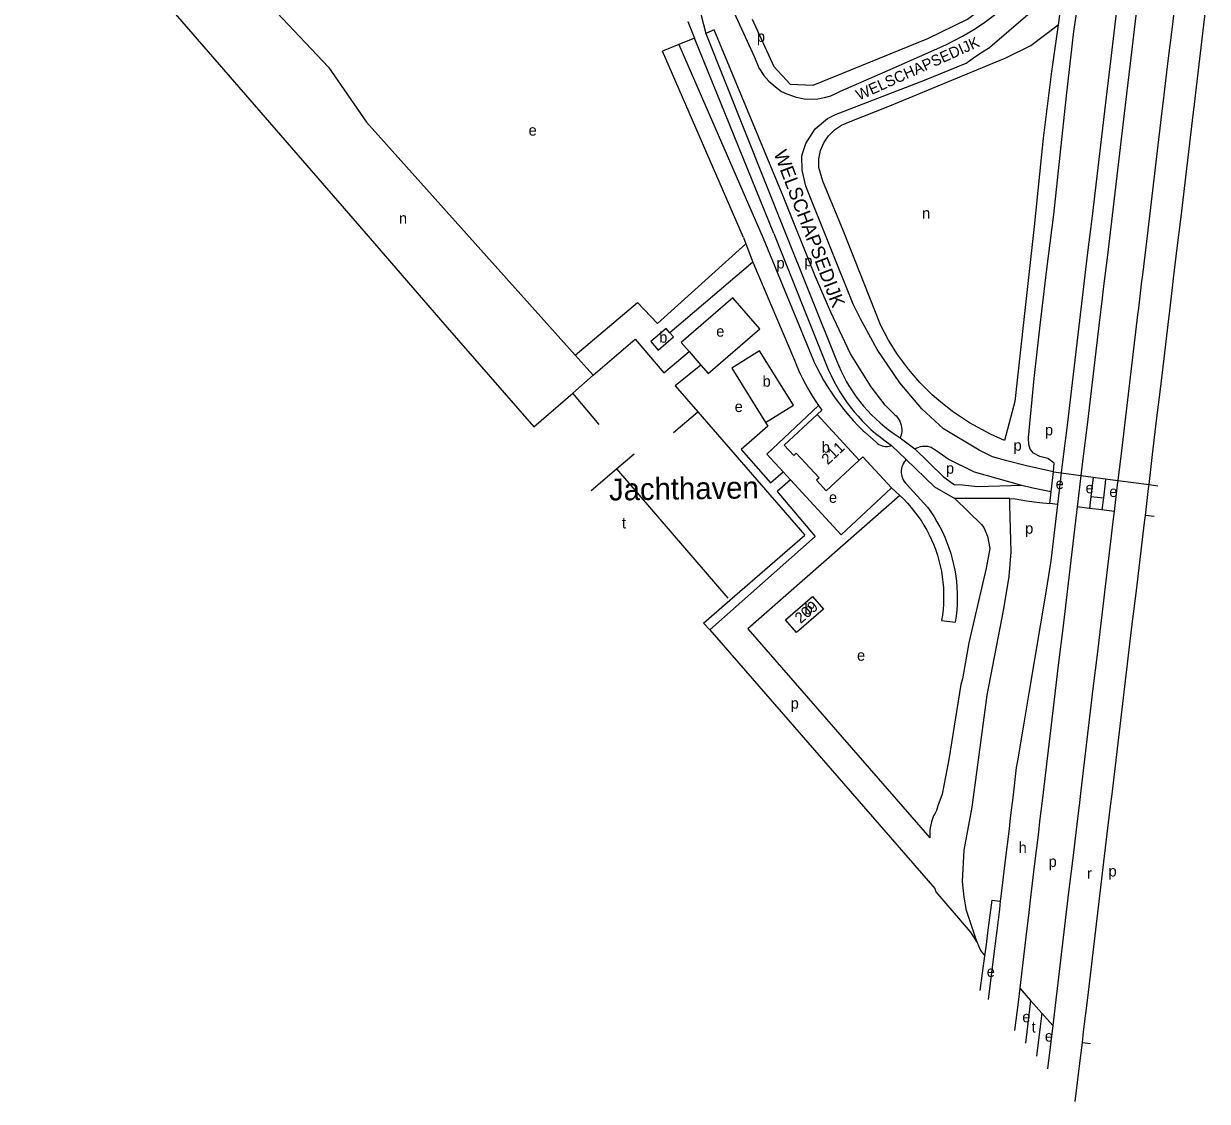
# Model space of a CAD drawing. Extents: x 156066 to 157805, y 383432 to 385631.
# Drawn here: x 157346 to 157778.7, y 383431.9 to 383825.9 of the extents above; entities that cross this region are included whole.
import ezdxf

# ---------------------------------------------------------------- set-up
doc = ezdxf.new("R2010")
doc.units = 0
for name, color, linetype in [('BLT_Basislijn', 7, 'Continuous'), ('BLT_Bebouwing', 7, 'Continuous'), ('BLT_Centroide', 7, 'Continuous'), ('BLT_Huisnummer', 7, 'Continuous'), ('BLT_Straatnaam', 7, 'Continuous'), ('BLT_Straatnaam_verkleind', 7, 'Continuous'), ('BLT_Terrein_beschrifting', 7, 'Continuous'), ('BLT_Vlakafsluiter', 7, 'Continuous')]:
    doc.layers.add(name, color=color, linetype=linetype)

msp = doc.modelspace()

# ---------------------------------------------------------------- linework, layer by layer
at = {"layer": 'BLT_Basislijn'}
for p, q in [((157457.51, 383809.98), (157438.58, 383829.98)), ((157593.54, 383829.35), (157595.4, 383822.3)), ((157588.75, 383826.7), (157591.23, 383820.59)), ((157591.23, 383820.59), (157585.48, 383818.23)), ((157620.2, 383749.22), (157591.23, 383820.59)), ((157595.4, 383822.3), (157623.9, 383750.73)), ((157585.48, 383818.23), (157579.57, 383815.8)), ((157609.12, 383747.66), (157579.57, 383815.8)), ((157609.12, 383747.66), (157609.99, 383745.39)), ((157620.2, 383749.22), (157639.4, 383701.34)), ((157623.9, 383750.73), (157643.13, 383702.79)), ((157609.99, 383745.39), (157612.52, 383738.71)), ((157612.52, 383738.71), (157582.28, 383712.84)), ((157612.52, 383738.71), (157627.82, 383702.89)), ((157554.26, 383697.33), (157569.55, 383710.59)), ((157547.66, 383704.7), (157554.26, 383697.33)), ((157589.26, 383706.06), (157593.56, 383701.09)), ((157546.74, 383690.8), (157554.26, 383697.33)), ((157556.36, 383679.38), (157546.74, 383690.8)), ((157660.91, 383686.48), (157664.41, 383683.03)), ((157583.53, 383676.38), (157592.43, 383684.01)), ((157592.43, 383684.01), (157631.6, 383638.86)), ((157636.09, 383682.98), (157637.81, 383684.64)), ((157653.46, 383676.5), (157657.69, 383672.85)), ((157666.44, 383674.45), (157671.74, 383670.48)), ((157668.6, 383666.56), (157663.31, 383671.71)), ((157562.77, 383663.15), (157569.19, 383668.67)), ((157651.49, 383666.3), (157652.78, 383667.56)), ((157652.78, 383667.56), (157663.3, 383656.22)), ((157668.6, 383666.56), (157668.05, 383665.77)), ((157553.51, 383655.2), (157562.77, 383663.15)), ((157562.77, 383663.15), (157603.47, 383615.84)), ((157623.62, 383662.07), (157626.29, 383659.16)), ((157721.64, 383654.79), (157722.42, 383662.04)), ((157722.42, 383662.04), (157725.33, 383661.66)), ((157732.51, 383660.7), (157736.97, 383660.11)), ((157663.3, 383656.22), (157666.29, 383653.4)), ((157668.74, 383657.53), (157676.42, 383649.08)), ((157736.97, 383660.11), (157741.52, 383659.51)), ((157741.52, 383659.51), (157745.99, 383658.92)), ((157757.39, 383657.41), (157760.57, 383656.99)), ((157666.29, 383653.4), (157610.71, 383604.63)), ((157706.46, 383652.32), (157686.36, 383652.25)), ((157721.11, 383650.52), (157721.64, 383654.79)), ((157736.13, 383653.03), (157740.69, 383652.49)), ((157723.95, 383650.16), (157721.11, 383650.52)), ((157735.61, 383648.7), (157731.14, 383649.26)), ((157740.16, 383648.12), (157735.61, 383648.7)), ((157744.63, 383647.56), (157740.16, 383648.12)), ((157759.21, 383645.73), (157756.04, 383646.13)), ((157604.13, 383615.09), (157631.6, 383638.86)), ((157596.81, 383604.28), (157679.07, 383509.71)), ((157610.71, 383604.63), (157677.29, 383528.31)), ((157681.54, 383607.66), (157686.57, 383607.13)), ((157689.24, 383586.43), (157688.6, 383584.32)), ((157680.25, 383539.93), (157679.74, 383538.29)), ((157679.07, 383509.71), (157679.5, 383508.54)), ((157695.7, 383472.46), (157697.43, 383485.16)), ((157710.11, 383473.27), (157714.11, 383468.75)), ((157714.11, 383468.75), (157718.18, 383464.15)), ((157718.18, 383464.15), (157722.17, 383459.64)), ((157733.01, 383453.43), (157735.99, 383453.06))]:
    msp.add_line(p, q, dxfattribs=at)
for points in [[(157722.42, 383662.04), (157722.67, 383665.22), (157720.34, 383666.94), (157717.53, 383667.7), (157715.18, 383668.86), (157713.89, 383670.39), (157713.43, 383672.1), (157713.37, 383674.52), (157715.42, 383696.22), (157717.58, 383715.61), (157720.01, 383736.12), (157722.63, 383756.17), (157727.24, 383799.44), (157729.87, 383823.04), (157736.09, 383864.84), (157743.57, 383910.3), (157751.03, 383956.19), (157757.33, 384004.1), (157760.96, 384035.06), (157763.25, 384061.94)], [(157346.04, 383893.34), (157407.92, 383821.99), (157470.36, 383750), (157500, 383715.82)], [(157612.35, 383827.53), (157620.27, 383810.26), (157626.26, 383803.73), (157634.61, 383803.39), (157676.59, 383820.43), (157691.04, 383827.5), (157700.2, 383834.34), (157708.27, 383840.98)], [(157699.19, 383817.3), (157713.05, 383829.25), (157724.1, 383841.83)], [(157726.44, 383841.44), (157725.63, 383836.21), (157724.13, 383825.48)], [(157603.63, 383834.36), (157608.4, 383823.97), (157613.18, 383813.58), (157614.72, 383809.78), (157616.56, 383806.93), (157618.4, 383804.81), (157620.8, 383802.78), (157623.01, 383801.12), (157625.04, 383800.2), (157628.08, 383799.09), (157631.39, 383798.45), (157633.99, 383798.32), (157636.28, 383798.45), (157638.81, 383798.86), (157641.04, 383799.51), (157642.95, 383800.29), (157644.67, 383801.16)], [(157644.67, 383801.16), (157663.88, 383809.64), (157683.09, 383818.12), (157689.23, 383821.3), (157693.97, 383824.16), (157697.41, 383826.47), (157700.75, 383828.94), (157705.02, 383832.45), (157710.41, 383837.51)], [(157753.46, 383836.1), (157751.98, 383823.69), (157750.49, 383811.28), (157749.19, 383800.26), (157748.08, 383790.96), (157746.6, 383778.55), (157745.11, 383766.13), (157743.63, 383753.72), (157742.15, 383741.31), (157740.66, 383728.9), (157740.26, 383725.56)], [(157746.26, 383836.96), (157744.78, 383824.55), (157743.29, 383812.14), (157741.99, 383801.12)], [(157767.28, 383837.14), (157765.8, 383824.73), (157764.31, 383812.32), (157762.83, 383799.91), (157762.68, 383798.65), (157762.11, 383793.85), (157760.62, 383781.44), (157759.14, 383769.03), (157757.66, 383756.61), (157756.17, 383744.2), (157754.85, 383733.12), (157754.69, 383731.79), (157753.51, 383721.89)], [(157764.72, 383718.78), (157766.11, 383730.43), (157766.27, 383731.75), (157767.59, 383742.84), (157769.08, 383755.25), (157770.56, 383767.66), (157772.04, 383780.07), (157773.53, 383792.49), (157774.1, 383797.28), (157774.25, 383798.54), (157775.73, 383810.95), (157777.21, 383823.36), (157778.7, 383835.78)], [(157704.52, 383673.56), (157699.44, 383675.78), (157691.82, 383679.96), (157685.5, 383684.15), (157680.51, 383688.11), (157678.13, 383690.22), (157673.62, 383694.72), (157669.46, 383699.53), (157665.42, 383704.98), (157662.15, 383710.22), (157659.25, 383715.79), (157645.65, 383750), (157638.16, 383768.26), (157636.68, 383773.34), (157636.68, 383776.48), (157637.34, 383779.55), (157638.55, 383782.3), (157640.22, 383784.9), (157642.39, 383787.1), (157644.98, 383788.79), (157647.55, 383789.83), (157662.64, 383795.84), (157705.05, 383813.33), (157714.13, 383817.93), (157724.13, 383825.48)], [(157724.13, 383825.48), (157721.73, 383808.33), (157718.74, 383784.05), (157715.44, 383751.67), (157711.54, 383716.59), (157708.39, 383687.81), (157704.52, 383673.56)], [(157660.91, 383686.48), (157655.83, 383693.14), (157648.3, 383705.21), (157641.02, 383720.37), (157635.43, 383733.33), (157623.71, 383762.8), (157598.48, 383823.56), (157595.4, 383822.3)], [(157585.48, 383818.23), (157616.32, 383747.49), (157634.69, 383702.75), (157634.79, 383702.59)], [(157690.55, 383811.48), (157693.21, 383813.38), (157695.92, 383815.21), (157698.67, 383816.97), (157699.19, 383817.3)], [(157457.51, 383809.98), (157471.4, 383789.83), (157547.66, 383704.7)], [(157642.79, 383792.66), (157675.36, 383805.22), (157690.55, 383811.48)], [(157741.99, 383801.12), (157740.88, 383791.82), (157739.4, 383779.41), (157737.91, 383767), (157736.43, 383754.58), (157734.95, 383742.17), (157733.46, 383729.76), (157731.98, 383717.35), (157730.5, 383704.94), (157729.01, 383692.53), (157727.53, 383680.11), (157726.05, 383667.7), (157725.33, 383661.66)], [(157705.38, 383666.03), (157700.21, 383667.59), (157695.26, 383669.98), (157682.29, 383677.72), (157674.33, 383685.12), (157666.3, 383694.54), (157658.02, 383706.79), (157651.94, 383717.98), (157649.22, 383723.31), (157631.92, 383766.52), (157630.54, 383772.32), (157630.5, 383777.38), (157630.82, 383778.77), (157631.89, 383782.08), (157635.3, 383787.49), (157639.86, 383791.16), (157642.79, 383792.66)], [(157547.66, 383704.7), (157570.35, 383723.98), (157577.66, 383716.29), (157609.99, 383745.39)], [(157605.3, 383725.7), (157586.4, 383709.37), (157589.26, 383706.06)], [(157593.56, 383701.09), (157596.2, 383698.03), (157615.1, 383714.36), (157605.3, 383725.7)], [(157740.26, 383725.56), (157739.18, 383716.49), (157737.7, 383704.08), (157736.21, 383691.66), (157734.73, 383679.25), (157733.25, 383666.84), (157732.51, 383660.7)], [(157753.51, 383721.89), (157753.21, 383719.38), (157751.73, 383706.97), (157750.24, 383694.56), (157748.76, 383682.14), (157747.28, 383669.73), (157745.99, 383658.92)], [(157757.39, 383657.41), (157758.7, 383668.37), (157760.18, 383680.78), (157761.66, 383693.19), (157763.14, 383705.6), (157764.63, 383718.02), (157764.72, 383718.78)], [(157500, 383715.82), (157532.49, 383678.45), (157546.74, 383690.8)], [(157569.55, 383710.59), (157580.09, 383698.24), (157589.26, 383706.06)], [(157593.56, 383701.09), (157584.2, 383693.49), (157592.43, 383684.01)], [(157627.82, 383702.89), (157628.71, 383700.63), (157629.67, 383698.41), (157630.71, 383696.21), (157631.81, 383694.06), (157632.99, 383691.94), (157634.24, 383689.86), (157635.55, 383687.82), (157636.58, 383686.35)], [(157634.79, 383702.59), (157635.93, 383700.22), (157637.14, 383697.9), (157638.42, 383695.6), (157639.77, 383693.35), (157641.19, 383691.15), (157642.68, 383688.98), (157644.23, 383686.86), (157645.84, 383684.79), (157647.52, 383682.77), (157649.26, 383680.8), (157651.05, 383678.89), (157652.91, 383677.03), (157653.46, 383676.5)], [(157639.4, 383701.34), (157640.25, 383699.27), (157641.17, 383697.23), (157642.16, 383695.22), (157643.23, 383693.25), (157644.36, 383691.32), (157645.57, 383689.43), (157646.84, 383687.58), (157648.17, 383685.79), (157649.57, 383684.04), (157651.03, 383682.34), (157652.55, 383680.69), (157654.12, 383679.1), (157655.76, 383677.57), (157657.45, 383676.1), (157659.18, 383674.68), (157660.97, 383673.33), (157662.8, 383672.05), (157663.31, 383671.71)], [(157643.13, 383702.79), (157643.95, 383700.78), (157644.85, 383698.81), (157645.81, 383696.87), (157646.85, 383694.97), (157647.96, 383693.11), (157649.14, 383691.29), (157650.38, 383689.51), (157651.68, 383687.78), (157653.05, 383686.1), (157654.49, 383684.48), (157655.98, 383682.9), (157657.52, 383681.39), (157659.12, 383679.93), (157660.78, 383678.53), (157662.49, 383677.19), (157664.24, 383675.92), (157666.04, 383674.71), (157666.44, 383674.45)], [(157636.58, 383686.35), (157617.64, 383668.56), (157623.62, 383662.07)], [(157636.58, 383686.35), (157636.94, 383685.83), (157637.81, 383684.64)], [(157664.41, 383683.03), (157664.97, 383682.49), (157665.47, 383681.89), (157665.91, 383681.24), (157666.27, 383680.55), (157666.57, 383679.83), (157666.79, 383679.08), (157666.93, 383678.32), (157667, 383677.54), (157666.98, 383676.76), (157666.88, 383675.98), (157666.71, 383675.22), (157666.44, 383674.45)], [(157617.21, 383680.1), (157618.1, 383678.71), (157608.31, 383670.23), (157619.08, 383658.03), (157623.62, 383662.07)], [(157657.69, 383672.85), (157658.16, 383672.42), (157658.68, 383672.05), (157659.25, 383671.76), (157659.85, 383671.53), (157660.47, 383671.38), (157661.1, 383671.31), (157661.74, 383671.32), (157662.38, 383671.41), (157662.99, 383671.58), (157663.31, 383671.71)], [(157679.84, 383669.62), (157678.86, 383670.23), (157677.75, 383670.96), (157676.67, 383671.28), (157675.9, 383671.33), (157674.61, 383671.31), (157673.72, 383671.13), (157672.72, 383670.86), (157671.74, 383670.48)], [(157671.74, 383670.48), (157682.18, 383660.39), (157686.28, 383657.27)], [(157710.87, 383657.08), (157693.63, 383661.97), (157683.95, 383666.73), (157679.84, 383669.62)], [(157668.05, 383665.77), (157667.66, 383665.18), (157667.34, 383664.55), (157667.09, 383663.89), (157666.92, 383663.21), (157666.83, 383662.51), (157666.82, 383661.8), (157666.89, 383661.1), (157667.03, 383660.41), (157667.25, 383659.74), (157667.55, 383659.1), (157667.92, 383658.49), (157668.35, 383657.93), (157668.74, 383657.53)], [(157668.6, 383666.56), (157678.92, 383656.59), (157686.36, 383652.25)], [(157722.42, 383662.04), (157713.07, 383664.15), (157705.38, 383666.03)], [(157725.33, 383661.66), (157724.56, 383655.29), (157723.95, 383650.16)], [(157732.51, 383660.7), (157731.76, 383654.43), (157731.14, 383649.26)], [(157626.29, 383659.16), (157621.49, 383654.91), (157635.33, 383638.36), (157596.81, 383604.28)], [(157626.29, 383659.16), (157644.84, 383639.03), (157663.3, 383656.22)], [(157710.87, 383657.08), (157694.71, 383656.57), (157689.19, 383657.14), (157686.28, 383657.27)], [(157721.64, 383654.79), (157714.94, 383656.04), (157710.87, 383657.08)], [(157736.97, 383660.11), (157736.13, 383653.03)], [(157741.52, 383659.51), (157741.33, 383657.85), (157740.69, 383652.49)], [(157745.99, 383658.92), (157745.79, 383657.32), (157744.63, 383647.56)], [(157756.04, 383646.13), (157757.21, 383655.96), (157757.39, 383657.41)], [(157666.29, 383653.4), (157667.73, 383652), (157669.11, 383650.55), (157670.44, 383649.04), (157671.7, 383647.48), (157672.9, 383645.86), (157674.04, 383644.21), (157675.11, 383642.5), (157676.11, 383640.76), (157677.04, 383638.98), (157677.9, 383637.16), (157678.68, 383635.31), (157679.4, 383633.43), (157680.03, 383631.53), (157680.59, 383629.6), (157681.08, 383627.65), (157681.48, 383625.68), (157681.81, 383623.7), (157682.05, 383621.7), (157682.22, 383619.7), (157682.31, 383617.69), (157682.32, 383615.68), (157682.24, 383613.67), (157682.09, 383611.67), (157681.86, 383609.67), (157681.54, 383607.66)], [(157686.36, 383652.25), (157696.14, 383642.82), (157697.01, 383641.66), (157698.32, 383638.54), (157699.15, 383634.06), (157697.89, 383626.88), (157691.55, 383599.57), (157689.24, 383586.43)], [(157694.51, 383490.02), (157690.68, 383501.76), (157689.77, 383506.58), (157689.24, 383512.36), (157689.81, 383523.73), (157692.76, 383539.46), (157698.17, 383580.44), (157704.26, 383612), (157706.23, 383623.8), (157707.05, 383632.82), (157706.56, 383649.89), (157706.46, 383652.32)], [(157706.46, 383652.32), (157708.42, 383652.14), (157712.61, 383651.43), (157717.32, 383650.88), (157721.11, 383650.52)], [(157736.13, 383653.03), (157735.61, 383648.7)], [(157740.69, 383652.49), (157740.16, 383648.12)], [(157676.42, 383649.08), (157677.64, 383647.37), (157678.79, 383645.61), (157679.88, 383643.8), (157680.9, 383641.96), (157681.85, 383640.08), (157682.72, 383638.17), (157683.52, 383636.22), (157684.25, 383634.24), (157684.9, 383632.24), (157685.47, 383630.22), (157685.97, 383628.17), (157686.39, 383626.11), (157686.73, 383624.03), (157686.99, 383621.94), (157687.17, 383619.85), (157687.27, 383617.74), (157687.29, 383615.64), (157687.24, 383613.53), (157687.1, 383611.43), (157686.88, 383609.34), (157686.57, 383607.13)], [(157723.95, 383650.16), (157723.08, 383642.88), (157721.6, 383630.47), (157721.3, 383627.98), (157719.64, 383618.11), (157717.57, 383605.77), (157715.5, 383593.43), (157713.43, 383581.09), (157711.36, 383568.75), (157709.29, 383556.4), (157708.88, 383553.94), (157707.69, 383544.01), (157706.68, 383535.53), (157706.21, 383531.59), (157704.72, 383519.18), (157703.24, 383506.77), (157703.03, 383505.06)], [(157731.14, 383649.26), (157730.28, 383642.02), (157728.8, 383629.61), (157727.31, 383617.19), (157725.83, 383604.78), (157724.35, 383592.37), (157722.86, 383579.96), (157721.38, 383567.55), (157719.9, 383555.14), (157718.41, 383542.72), (157717.4, 383534.25), (157716.93, 383530.31), (157715.45, 383517.9), (157713.96, 383505.49), (157713.42, 383500.96), (157712.48, 383493.08), (157711, 383480.67), (157710.11, 383473.27)], [(157744.63, 383647.56), (157744.31, 383644.91), (157742.83, 383632.5), (157741.35, 383620.09), (157739.86, 383607.67), (157738.38, 383595.26), (157736.9, 383582.85), (157735.41, 383570.44), (157733.93, 383558.03), (157732.45, 383545.62), (157731.92, 383541.19), (157730.96, 383533.2), (157729.48, 383520.79), (157728, 383508.38), (157726.52, 383495.97), (157725.03, 383483.56), (157723.55, 383471.15), (157722.17, 383459.64)], [(157733.01, 383453.43), (157733.49, 383457.37), (157734.97, 383469.78), (157736.45, 383482.19), (157737.93, 383494.6), (157739.42, 383507.02), (157740.9, 383519.43), (157742.38, 383531.84), (157743.34, 383539.83), (157743.87, 383544.25), (157745.35, 383556.66), (157746.83, 383569.07), (157748.32, 383581.49), (157749.8, 383593.9), (157751.28, 383606.31), (157752.76, 383618.72), (157754.25, 383631.13), (157755.73, 383643.55), (157756.04, 383646.13)], [(157596.81, 383604.28), (157594.5, 383606.76), (157604.13, 383615.09)], [(157688.6, 383584.32), (157684.19, 383556.86), (157681.73, 383544.19), (157680.25, 383539.93)], [(157679.74, 383538.29), (157679.16, 383537.31), (157678.66, 383536.29), (157678.23, 383535.24), (157677.87, 383534.16), (157677.59, 383533.06), (157677.39, 383531.95), (157677.27, 383530.82), (157677.23, 383529.68), (157677.27, 383528.55), (157677.29, 383528.31)], [(157679.5, 383508.54), (157691.95, 383493.87), (157694.51, 383490.02)], [(157703.03, 383505.06), (157702.7, 383502.24), (157701.75, 383494.36), (157700.21, 383481.96), (157698.55, 383469.14)], [(157698.61, 383494.47), (157700.02, 383505.5), (157703.03, 383505.06)], [(157697.43, 383485.16), (157697.85, 383488.25), (157698.61, 383494.47)], [(157694.51, 383490.02), (157695.76, 383487.07), (157697.43, 383485.16)], [(157710.11, 383473.27), (157709.51, 383468.25), (157708.27, 383457.81)], [(157714.11, 383468.75), (157713.98, 383467.72), (157712.5, 383455.31), (157712.24, 383453.17)], [(157718.18, 383464.15), (157717.6, 383459.27), (157716.3, 383448.44)], [(157722.17, 383459.64), (157720.28, 383443.8)], [(157730.45, 383431.94), (157732, 383444.96), (157733.01, 383453.43)]]:
    msp.add_lwpolyline(points, dxfattribs=at)
at = {"layer": 'BLT_Bebouwing'}
msp.add_line((157651.49, 383666.3), (157636.09, 383682.98), dxfattribs=at)
for points in [[(157582.28, 383712.84), (157580.87, 383714.48), (157575.25, 383709.68), (157577.93, 383706.53), (157583.56, 383711.34), (157582.28, 383712.84)], [(157614.99, 383706.32), (157604.85, 383699.97), (157617.21, 383680.1)], [(157617.21, 383680.1), (157627.4, 383686.43), (157614.99, 383706.32)], [(157636.09, 383682.98), (157624.02, 383671.8), (157627.53, 383668.01), (157628.42, 383668.85), (157636.78, 383659.85), (157635.88, 383658.96), (157639.42, 383655.14), (157651.49, 383666.3)], [(157628.49, 383603.37), (157624.51, 383607.99), (157634.38, 383616.48), (157638.36, 383611.86), (157628.49, 383603.37)]]:
    msp.add_lwpolyline(points, dxfattribs=at)
at = {"layer": 'BLT_Vlakafsluiter'}
for p, q in [((157725.33, 383661.66), (157732.51, 383660.7)), ((157745.99, 383658.92), (157757.39, 383657.41))]:
    msp.add_line(p, q, dxfattribs=at)

# ---------------------------------------------------------------- texts
at = {"layer": 'BLT_Centroide'}
for s, p in [('p', (157614.04, 383819.19)), ('e', (157530.6, 383784.94)), ('n', (157483.21, 383752.76)), ('n', (157674.43, 383754.6)), ('p', (157621.21, 383736.39)), ('p', (157631.4, 383737.2)), ('b', (157578.35, 383709.25)), ('e', (157599.18, 383711.46)), ('b', (157616.12, 383693.17)), ('e', (157605.95, 383683.9)), ('p', (157719.35, 383675.38)), ('b', (157637.75, 383669.06)), ('p', (157707.85, 383669.78)), ('p', (157683.16, 383661.37)), ('e', (157723.25, 383655.74)), ('e', (157734.2, 383654.2)), ('e', (157742.89, 383652.84)), ('e', (157640.38, 383650.72)), ('t', (157564.71, 383641.36)), ('p', (157712.1, 383639.42)), ('b', (157631.43, 383609.94)), ('e', (157650.66, 383593)), ('p', (157626.4, 383575.48)), ('h', (157709.72, 383522.72)), ('p', (157720.67, 383517.63)), ('r', (157734.7, 383513.31)), ('p', (157742.57, 383514.12)), ('e', (157698.06, 383477.4)), ('e', (157711.07, 383460.84)), ('t', (157714.47, 383457.09)), ('e', (157719.31, 383453.79))]:
    msp.add_text(s, height=4, dxfattribs=at).set_placement(p)
at = {"layer": 'BLT_Huisnummer'}
for s, rotation, p in [('211', 43.1494, (157639.95, 383664.4)), ('209', 40.6829, (157630.01, 383606.36))]:
    msp.add_text(s, height=4, rotation=rotation, dxfattribs=at).set_placement(p)
at = {"layer": 'BLT_Straatnaam'}
msp.add_text('WELSCHAPSEDIJK', height=5, rotation=290.8385, dxfattribs=at).set_placement((157620.11, 383778.57))
at = {"layer": 'BLT_Straatnaam_verkleind'}
msp.add_text('WELSCHAPSEDIJK', height=4, rotation=24.1803, dxfattribs=at).set_placement((157651.38, 383797.72))
at = {"layer": 'BLT_Terrein_beschrifting'}
msp.add_text('Jachthaven', height=8, rotation=0.8717, dxfattribs=at).set_placement((157560.06, 383651.55))

doc.saveas('drawing.dxf')
